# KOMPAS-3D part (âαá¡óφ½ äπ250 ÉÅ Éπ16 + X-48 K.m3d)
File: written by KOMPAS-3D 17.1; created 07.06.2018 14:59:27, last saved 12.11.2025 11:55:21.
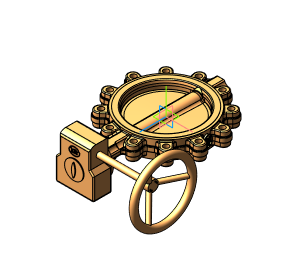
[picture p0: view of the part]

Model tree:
1. Операция без истории:7  (labels: Сталь 20  ГОСТ 1050-2013)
